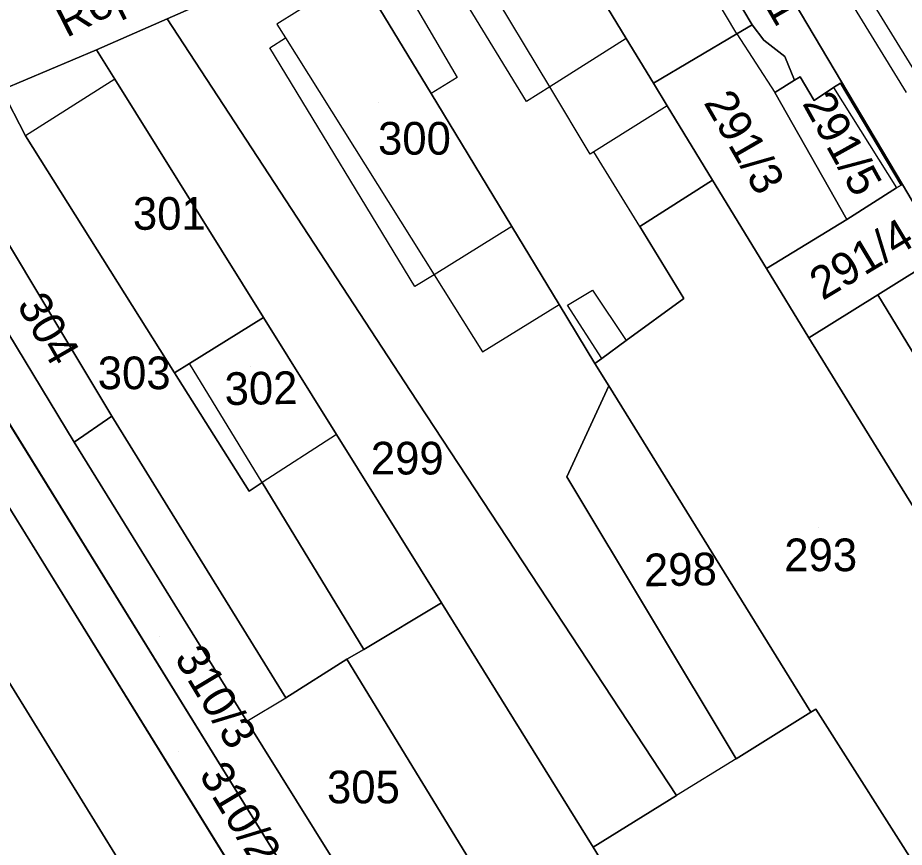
# Model space of a CAD drawing. Extents: x -263943 to -261149, y -1236934 to -1230686.
# Drawn here: x -262618.9 to -262564.6, y -1235644 to -1235593.2 of the extents above; entities that cross this region are included whole.
import ezdxf

# ---------------------------------------------------------------- set-up
doc = ezdxf.new("R2010")
doc.units = 0
for name, color, linetype in [('body_kn', 7, 'Continuous'), ('kladpar_druhypozemkov', 7, 'Continuous'), ('kladpar_hranice', 7, 'Continuous'), ('kladpar_parcelnecisla', 7, 'Continuous'), ('kladpar_plochy', 7, 'Continuous'), ('popisy', 7, 'Continuous'), ('zappar_hrandruhpozemk', 7, 'Continuous')]:
    doc.layers.add(name, color=color, linetype=linetype)

msp = doc.modelspace()

# ---------------------------------------------------------------- linework, layer by layer
at = {"layer": 'body_kn'}
for p, q in [((-262609.72, -1235593.27), (-262609.72, -1235593.27)), ((-262603, -1235593.61), (-262603, -1235593.61)), ((-262573.91, -1235593.64), (-262573.91, -1235593.64)), ((-262573.91, -1235593.64), (-262573.91, -1235593.64)), ((-262602.48, -1235594.44), (-262602.48, -1235594.44)), ((-262602.48, -1235594.44), (-262602.48, -1235594.44)), ((-262574.85, -1235594.19), (-262574.85, -1235594.19)), ((-262574.85, -1235594.19), (-262574.85, -1235594.19)), ((-262581.61, -1235594.48), (-262581.61, -1235594.48)), ((-262581.61, -1235594.48), (-262581.61, -1235594.48)), ((-262573.18, -1235594.59), (-262573.18, -1235594.59)), ((-262614.05, -1235595.18), (-262614.05, -1235595.18)), ((-262603.43, -1235595.05), (-262603.43, -1235595.05)), ((-262571.9, -1235595.58), (-262571.9, -1235595.58)), ((-262571.9, -1235595.58), (-262571.9, -1235595.58)), ((-262612.93, -1235596.98), (-262612.93, -1235596.98)), ((-262612.93, -1235596.98), (-262612.93, -1235596.98)), ((-262591.97, -1235596.87), (-262591.97, -1235596.87)), ((-262571.31, -1235597.03), (-262571.31, -1235597.03)), ((-262570.97, -1235596.82), (-262570.97, -1235596.82)), ((-262586.3, -1235597.44), (-262586.3, -1235597.44)), ((-262579.94, -1235597.22), (-262579.94, -1235597.22)), ((-262568.92, -1235597.49), (-262568.92, -1235597.49)), ((-262568.92, -1235597.49), (-262568.92, -1235597.49)), ((-262568.49, -1235597.22), (-262568.49, -1235597.22)), ((-262593.56, -1235597.85), (-262593.56, -1235597.85)), ((-262572.51, -1235597.78), (-262572.51, -1235597.78)), ((-262572.51, -1235597.78), (-262572.51, -1235597.78)), ((-262587.72, -1235598.33), (-262587.72, -1235598.33)), ((-262579.1, -1235598.6), (-262579.1, -1235598.6)), ((-262579.1, -1235598.6), (-262579.1, -1235598.6)), ((-262570.11, -1235598.27), (-262570.11, -1235598.27)), ((-262618.4, -1235600.43), (-262618.4, -1235600.43)), ((-262618.4, -1235600.43), (-262618.4, -1235600.43)), ((-262583.59, -1235601.41), (-262583.59, -1235601.41)), ((-262583.59, -1235601.41), (-262583.59, -1235601.41)), ((-262583.83, -1235601.56), (-262583.83, -1235601.56)), ((-262576.33, -1235603.15), (-262576.33, -1235603.15)), ((-262565.07, -1235603.63), (-262565.07, -1235603.63)), ((-262565.07, -1235603.63), (-262565.07, -1235603.63)), ((-262564.78, -1235603.46), (-262564.78, -1235603.46)), ((-262564.7, -1235603.41), (-262564.7, -1235603.41)), ((-262568.11, -1235605.57), (-262568.11, -1235605.57)), ((-262588.62, -1235605.99), (-262588.62, -1235605.99)), ((-262588.62, -1235605.99), (-262588.62, -1235605.99)), ((-262580.78, -1235605.99), (-262580.78, -1235605.99)), ((-262580.78, -1235605.99), (-262580.78, -1235605.99)), ((-262573.03, -1235608.57), (-262573.03, -1235608.57)), ((-262593.38, -1235608.94), (-262593.38, -1235608.94)), ((-262594.56, -1235609.67), (-262594.56, -1235609.67)), ((-262583.68, -1235609.88), (-262583.68, -1235609.88)), ((-262566.2, -1235610.17), (-262566.2, -1235610.17)), ((-262566.2, -1235610.17), (-262566.2, -1235610.17)), ((-262578.08, -1235610.4), (-262578.08, -1235610.4)), ((-262585.72, -1235610.76), (-262585.72, -1235610.76)), ((-262585.22, -1235610.81), (-262585.22, -1235610.81)), ((-262603.82, -1235611.57), (-262603.82, -1235611.57)), ((-262570.44, -1235612.81), (-262570.44, -1235612.81)), ((-262581.61, -1235612.97), (-262581.61, -1235612.97)), ((-262590.41, -1235613.67), (-262590.41, -1235613.67)), ((-262608.35, -1235614.37), (-262608.35, -1235614.37)), ((-262583.53, -1235614.37), (-262583.53, -1235614.37)), ((-262583.53, -1235614.37), (-262583.53, -1235614.37)), ((-262583.11, -1235614.07), (-262583.11, -1235614.07)), ((-262583.11, -1235614.07), (-262583.11, -1235614.07)), ((-262609.27, -1235614.94), (-262609.27, -1235614.94)), ((-262594.84, -1235616.03), (-262594.84, -1235616.03)), ((-262582.68, -1235615.74), (-262582.68, -1235615.74)), ((-262582.68, -1235615.74), (-262582.68, -1235615.74)), ((-262567.81, -1235617.07), (-262567.81, -1235617.07)), ((-262613.11, -1235617.59), (-262613.11, -1235617.59)), ((-262599.36, -1235618.72), (-262599.36, -1235618.72)), ((-262599.36, -1235618.72), (-262599.36, -1235618.72)), ((-262615.41, -1235619.19), (-262615.41, -1235619.19)), ((-262585.25, -1235621.32), (-262585.25, -1235621.32)), ((-262603.91, -1235621.67), (-262603.91, -1235621.67)), ((-262603.91, -1235621.67), (-262603.91, -1235621.67)), ((-262604.71, -1235622.19), (-262604.71, -1235622.19)), ((-262592.93, -1235629.02), (-262592.93, -1235629.02)), ((-262597.69, -1235631.89), (-262597.69, -1235631.89)), ((-262598.72, -1235632.48), (-262598.72, -1235632.48)), ((-262598.72, -1235632.48), (-262598.72, -1235632.48)), ((-262602.46, -1235634.84), (-262602.46, -1235634.84)), ((-262570.01, -1235635.54), (-262570.01, -1235635.54)), ((-262570.31, -1235635.73), (-262570.31, -1235635.73)), ((-262604.85, -1235636.28), (-262604.85, -1235636.28)), ((-262604.85, -1235636.28), (-262604.85, -1235636.28)), ((-262574.89, -1235638.57), (-262574.89, -1235638.57)), ((-262574.89, -1235638.57), (-262574.89, -1235638.57)), ((-262578.54, -1235640.83), (-262578.54, -1235640.83)), ((-262583.63, -1235643.98), (-262583.63, -1235643.98))]:
    msp.add_line(p, q, dxfattribs=at)
at = {"layer": 'kladpar_druhypozemkov'}
for p, q in [((-262596.8, -1235598.39), (-262596.8, -1235598.39)), ((-262573.34, -1235600.62), (-262573.34, -1235600.62)), ((-262567.56, -1235600.92), (-262567.56, -1235600.92)), ((-262610.05, -1235604.24), (-262610.05, -1235604.24)), ((-262567.91, -1235607.64), (-262567.91, -1235607.64)), ((-262611.9, -1235614.03), (-262611.9, -1235614.03)), ((-262604.65, -1235614.59), (-262604.65, -1235614.59)), ((-262595.9, -1235619.24), (-262595.9, -1235619.24)), ((-262569.85, -1235624.44), (-262569.85, -1235624.44)), ((-262578.8, -1235626.44), (-262578.8, -1235626.44)), ((-262610.17, -1235631.1), (-262610.17, -1235631.1)), ((-262609.01, -1235638.15), (-262609.01, -1235638.15)), ((-262598.15, -1235639.39), (-262598.15, -1235639.39))]:
    msp.add_line(p, q, dxfattribs=at)
at = {"layer": 'kladpar_hranice'}
for p, q in [((-262598.02, -1235652.59), (-262629.39, -1235601.96)), ((-262629.39, -1235601.96), (-262598.02, -1235652.59)), ((-262565.36, -1235710.5), (-262631.97, -1235602.9)), ((-262631.97, -1235602.9), (-262565.36, -1235710.5))]:
    msp.add_line(p, q, dxfattribs=at)
for points in [[(-262532.65, -1235562.1), (-262539.93, -1235564.98), (-262540.35, -1235564.47), (-262546.13, -1235566.81), (-262550.31, -1235568.5), (-262550.6, -1235568.62), (-262559.42, -1235572.29), (-262564.18, -1235574.14), (-262569.31, -1235576.04), (-262578.87, -1235579.57), (-262581.75, -1235580.64), (-262588.52, -1235583.14), (-262593.39, -1235585.64), (-262594.97, -1235586.46), (-262599.16, -1235588.62), (-262609.72, -1235593.27), (-262614.05, -1235595.18), (-262619.84, -1235597.63)], [(-262562.18, -1235607.66), (-262564.7, -1235603.41), (-262578.87, -1235579.57), (-262569.31, -1235576.04), (-262542, -1235620.28), (-262551.28, -1235626.02), (-262555.42, -1235619.05), (-262562.18, -1235607.66)], [(-262571.9, -1235595.58), (-262573.18, -1235594.59), (-262573.91, -1235593.64), (-262577.58, -1235587.46), (-262578.5, -1235588.03), (-262581.19, -1235583.29), (-262586.99, -1235585.65), (-262587.03, -1235585.58), (-262588.52, -1235583.14), (-262581.75, -1235580.64), (-262578.87, -1235579.57), (-262564.7, -1235603.41), (-262564.78, -1235603.46), (-262568.49, -1235597.22), (-262568.92, -1235597.49), (-262570.11, -1235598.27), (-262570.97, -1235596.82), (-262571.31, -1235597.03), (-262571.9, -1235595.58)], [(-262580.78, -1235605.99), (-262578.08, -1235610.4), (-262581.61, -1235612.97), (-262583.11, -1235614.07), (-262583.53, -1235614.37), (-262585.72, -1235610.76), (-262588.62, -1235605.99), (-262593.56, -1235597.85), (-262596.41, -1235593.15), (-262598.03, -1235590.49), (-262599.16, -1235588.62), (-262594.97, -1235586.46), (-262593.39, -1235585.64), (-262588.52, -1235583.14), (-262587.03, -1235585.58), (-262586.99, -1235585.65), (-262581.61, -1235594.48), (-262579.94, -1235597.22), (-262579.1, -1235598.6), (-262576.33, -1235603.15), (-262580.78, -1235605.99)], [(-262573.91, -1235593.64), (-262574.85, -1235594.19), (-262579.94, -1235597.22), (-262581.61, -1235594.48), (-262586.99, -1235585.65), (-262581.19, -1235583.29), (-262578.5, -1235588.03), (-262577.58, -1235587.46), (-262573.91, -1235593.64)], [(-262583.53, -1235614.37), (-262582.68, -1235615.74), (-262585.25, -1235621.32), (-262574.89, -1235638.57), (-262570.31, -1235635.73), (-262570.01, -1235635.54), (-262563.41, -1235645.91), (-262577.29, -1235654.35), (-262583.63, -1235643.98), (-262578.54, -1235640.83), (-262594.84, -1235616.03), (-262609.72, -1235593.27), (-262599.16, -1235588.62), (-262598.03, -1235590.49), (-262596.41, -1235593.15), (-262593.56, -1235597.85), (-262588.62, -1235605.99), (-262585.72, -1235610.76), (-262583.53, -1235614.37)], [(-262599.36, -1235618.72), (-262603.82, -1235611.57), (-262612.93, -1235596.98), (-262614.05, -1235595.18), (-262609.72, -1235593.27), (-262594.84, -1235616.03), (-262578.54, -1235640.83), (-262583.63, -1235643.98), (-262592.93, -1235629.02), (-262599.36, -1235618.72)], [(-262574.85, -1235594.19), (-262573.91, -1235593.64), (-262573.18, -1235594.59), (-262571.9, -1235595.58), (-262571.31, -1235597.03), (-262572.51, -1235597.78), (-262568.11, -1235605.57), (-262573.03, -1235608.57), (-262576.33, -1235603.15), (-262579.1, -1235598.6), (-262579.94, -1235597.22), (-262574.85, -1235594.19)], [(-262618.4, -1235600.43), (-262619.84, -1235597.63), (-262614.05, -1235595.18), (-262612.93, -1235596.98), (-262603.82, -1235611.57), (-262608.35, -1235614.37), (-262609.27, -1235614.94), (-262618.4, -1235600.43)], [(-262572.51, -1235597.78), (-262571.31, -1235597.03), (-262570.97, -1235596.82), (-262570.11, -1235598.27), (-262568.92, -1235597.49), (-262568.49, -1235597.22), (-262564.78, -1235603.46), (-262565.07, -1235603.63), (-262568.11, -1235605.57), (-262572.51, -1235597.78)], [(-262598.72, -1235632.48), (-262602.46, -1235634.84), (-262613.11, -1235617.59), (-262623.75, -1235599.9), (-262619.84, -1235597.63), (-262618.4, -1235600.43), (-262609.27, -1235614.94), (-262604.71, -1235622.19), (-262603.91, -1235621.67), (-262597.69, -1235631.89), (-262598.72, -1235632.48)], [(-262623.75, -1235599.9), (-262613.11, -1235617.59), (-262615.41, -1235619.19), (-262626.51, -1235600.91), (-262623.75, -1235599.9)], [(-262626.51, -1235600.91), (-262615.41, -1235619.19), (-262604.85, -1235636.28), (-262595.63, -1235651.07), (-262598.02, -1235652.59)], [(-262565.36, -1235710.5), (-262570.45, -1235713.76), (-262571.77, -1235711.63), (-262582.68, -1235693.86), (-262604.66, -1235658.08), (-262612.77, -1235644.65), (-262624.69, -1235625.35), (-262636.17, -1235606.78), (-262637.36, -1235604.86), (-262631.97, -1235602.9)], [(-262553.45, -1235640.26), (-262563.08, -1235646.46), (-262563.41, -1235645.91), (-262570.01, -1235635.54), (-262570.31, -1235635.73), (-262582.68, -1235615.74), (-262583.53, -1235614.37), (-262583.11, -1235614.07), (-262581.61, -1235612.97), (-262578.08, -1235610.4), (-262580.78, -1235605.99), (-262576.33, -1235603.15), (-262573.03, -1235608.57), (-262570.44, -1235612.81), (-262567.81, -1235617.07), (-262553.45, -1235640.26)], [(-262565.07, -1235603.63), (-262564.78, -1235603.46), (-262564.7, -1235603.41), (-262562.18, -1235607.66), (-262566.2, -1235610.17), (-262570.44, -1235612.81), (-262573.03, -1235608.57), (-262568.11, -1235605.57), (-262565.07, -1235603.63)], [(-262544.28, -1235646.18), (-262566.2, -1235610.17), (-262562.18, -1235607.66), (-262555.42, -1235619.05), (-262551.28, -1235626.02), (-262540.46, -1235644.04), (-262544.28, -1235646.18)], [(-262566.2, -1235610.17), (-262544.28, -1235646.18), (-262548.46, -1235648.51), (-262553.45, -1235640.26), (-262567.81, -1235617.07), (-262570.44, -1235612.81), (-262566.2, -1235610.17)], [(-262603.91, -1235621.67), (-262604.71, -1235622.19), (-262609.27, -1235614.94), (-262608.35, -1235614.37), (-262603.82, -1235611.57), (-262599.36, -1235618.72), (-262592.93, -1235629.02), (-262597.69, -1235631.89), (-262603.91, -1235621.67)], [(-262582.68, -1235615.74), (-262570.31, -1235635.73), (-262574.89, -1235638.57), (-262585.25, -1235621.32), (-262582.68, -1235615.74)], [(-262571.62, -1235689.74), (-262589.21, -1235661.27), (-262586.06, -1235659.24), (-262592.23, -1235648.96), (-262595.63, -1235651.07), (-262604.85, -1235636.28), (-262615.41, -1235619.19), (-262613.11, -1235617.59), (-262602.46, -1235634.84), (-262598.72, -1235632.48), (-262589.42, -1235647.7), (-262582.83, -1235658.83), (-262565.92, -1235686.28), (-262571.62, -1235689.74)], [(-262634.41, -1235631.7), (-262630.76, -1235629.31), (-262629.74, -1235628.64), (-262625.1, -1235625.62), (-262624.69, -1235625.35), (-262612.77, -1235644.65), (-262622.65, -1235650.47), (-262634.41, -1235631.7)], [(-262565.92, -1235686.28), (-262582.83, -1235658.83), (-262589.42, -1235647.7), (-262598.72, -1235632.48), (-262597.69, -1235631.89), (-262592.93, -1235629.02), (-262583.63, -1235643.98), (-262577.29, -1235654.35), (-262560.13, -1235682.74), (-262565.92, -1235686.28)]]:
    msp.add_lwpolyline(points, dxfattribs=at)
at = {"layer": 'kladpar_plochy'}
msp.add_lwpolyline([(-262532.65, -1235562.1), (-262539.93, -1235564.98), (-262540.35, -1235564.47), (-262546.13, -1235566.81), (-262550.31, -1235568.5), (-262550.6, -1235568.62), (-262559.42, -1235572.29), (-262564.18, -1235574.14), (-262569.31, -1235576.04), (-262578.87, -1235579.57), (-262581.75, -1235580.64), (-262588.52, -1235583.14), (-262593.39, -1235585.64), (-262594.97, -1235586.46), (-262599.16, -1235588.62), (-262609.72, -1235593.27), (-262614.05, -1235595.18), (-262619.84, -1235597.63)], dxfattribs=at)
for points in [[(-262562.18, -1235607.66), (-262564.7, -1235603.41), (-262578.87, -1235579.57), (-262569.31, -1235576.04), (-262542, -1235620.28), (-262551.28, -1235626.02), (-262555.42, -1235619.05)], [(-262571.9, -1235595.58), (-262573.18, -1235594.59), (-262573.91, -1235593.64), (-262577.58, -1235587.46), (-262578.5, -1235588.03), (-262581.19, -1235583.29), (-262586.99, -1235585.65), (-262587.03, -1235585.58), (-262588.52, -1235583.14), (-262581.75, -1235580.64), (-262578.87, -1235579.57), (-262564.7, -1235603.41), (-262564.78, -1235603.46), (-262568.49, -1235597.22), (-262568.92, -1235597.49), (-262570.11, -1235598.27), (-262570.97, -1235596.82), (-262571.31, -1235597.03)], [(-262580.78, -1235605.99), (-262578.08, -1235610.4), (-262581.61, -1235612.97), (-262583.11, -1235614.07), (-262583.53, -1235614.37), (-262585.72, -1235610.76), (-262588.62, -1235605.99), (-262593.56, -1235597.85), (-262596.41, -1235593.15), (-262598.03, -1235590.49), (-262599.16, -1235588.62), (-262594.97, -1235586.46), (-262593.39, -1235585.64), (-262588.52, -1235583.14), (-262587.03, -1235585.58), (-262586.99, -1235585.65), (-262581.61, -1235594.48), (-262579.94, -1235597.22), (-262579.1, -1235598.6), (-262576.33, -1235603.15)], [(-262573.91, -1235593.64), (-262574.85, -1235594.19), (-262579.94, -1235597.22), (-262581.61, -1235594.48), (-262586.99, -1235585.65), (-262581.19, -1235583.29), (-262578.5, -1235588.03), (-262577.58, -1235587.46)], [(-262583.53, -1235614.37), (-262582.68, -1235615.74), (-262585.25, -1235621.32), (-262574.89, -1235638.57), (-262570.31, -1235635.73), (-262570.01, -1235635.54), (-262563.41, -1235645.91), (-262577.29, -1235654.35), (-262583.63, -1235643.98), (-262578.54, -1235640.83), (-262594.84, -1235616.03), (-262609.72, -1235593.27), (-262599.16, -1235588.62), (-262598.03, -1235590.49), (-262596.41, -1235593.15), (-262593.56, -1235597.85), (-262588.62, -1235605.99), (-262585.72, -1235610.76)], [(-262599.36, -1235618.72), (-262603.82, -1235611.57), (-262612.93, -1235596.98), (-262614.05, -1235595.18), (-262609.72, -1235593.27), (-262594.84, -1235616.03), (-262578.54, -1235640.83), (-262583.63, -1235643.98), (-262592.93, -1235629.02)], [(-262574.85, -1235594.19), (-262573.91, -1235593.64), (-262573.18, -1235594.59), (-262571.9, -1235595.58), (-262571.31, -1235597.03), (-262572.51, -1235597.78), (-262568.11, -1235605.57), (-262573.03, -1235608.57), (-262576.33, -1235603.15), (-262579.1, -1235598.6), (-262579.94, -1235597.22)], [(-262618.4, -1235600.43), (-262619.84, -1235597.63), (-262614.05, -1235595.18), (-262612.93, -1235596.98), (-262603.82, -1235611.57), (-262608.35, -1235614.37), (-262609.27, -1235614.94)], [(-262572.51, -1235597.78), (-262571.31, -1235597.03), (-262570.97, -1235596.82), (-262570.11, -1235598.27), (-262568.92, -1235597.49), (-262568.49, -1235597.22), (-262564.78, -1235603.46), (-262565.07, -1235603.63), (-262568.11, -1235605.57)], [(-262598.72, -1235632.48), (-262602.46, -1235634.84), (-262613.11, -1235617.59), (-262623.75, -1235599.9), (-262619.84, -1235597.63), (-262618.4, -1235600.43), (-262609.27, -1235614.94), (-262604.71, -1235622.19), (-262603.91, -1235621.67), (-262597.69, -1235631.89)], [(-262623.75, -1235599.9), (-262613.11, -1235617.59), (-262615.41, -1235619.19), (-262626.51, -1235600.91)], [(-262626.51, -1235600.91), (-262615.41, -1235619.19), (-262604.85, -1235636.28), (-262595.63, -1235651.07), (-262598.02, -1235652.59), (-262629.39, -1235601.96)], [(-262562.99, -1235708.99), (-262565.36, -1235710.5), (-262631.97, -1235602.9), (-262629.39, -1235601.96), (-262598.02, -1235652.59), (-262591.76, -1235662.87)], [(-262565.36, -1235710.5), (-262570.45, -1235713.76), (-262571.77, -1235711.63), (-262582.68, -1235693.86), (-262604.66, -1235658.08), (-262612.77, -1235644.65), (-262624.69, -1235625.35), (-262636.17, -1235606.78), (-262637.36, -1235604.86), (-262631.97, -1235602.9)], [(-262553.45, -1235640.26), (-262563.08, -1235646.46), (-262563.41, -1235645.91), (-262570.01, -1235635.54), (-262570.31, -1235635.73), (-262582.68, -1235615.74), (-262583.53, -1235614.37), (-262583.11, -1235614.07), (-262581.61, -1235612.97), (-262578.08, -1235610.4), (-262580.78, -1235605.99), (-262576.33, -1235603.15), (-262573.03, -1235608.57), (-262570.44, -1235612.81), (-262567.81, -1235617.07)], [(-262565.07, -1235603.63), (-262564.78, -1235603.46), (-262564.7, -1235603.41), (-262562.18, -1235607.66), (-262566.2, -1235610.17), (-262570.44, -1235612.81), (-262573.03, -1235608.57), (-262568.11, -1235605.57)], [(-262544.28, -1235646.18), (-262566.2, -1235610.17), (-262562.18, -1235607.66), (-262555.42, -1235619.05), (-262551.28, -1235626.02), (-262540.46, -1235644.04)], [(-262566.2, -1235610.17), (-262544.28, -1235646.18), (-262548.46, -1235648.51), (-262553.45, -1235640.26), (-262567.81, -1235617.07), (-262570.44, -1235612.81)], [(-262603.91, -1235621.67), (-262604.71, -1235622.19), (-262609.27, -1235614.94), (-262608.35, -1235614.37), (-262603.82, -1235611.57), (-262599.36, -1235618.72), (-262592.93, -1235629.02), (-262597.69, -1235631.89)], [(-262582.68, -1235615.74), (-262570.31, -1235635.73), (-262574.89, -1235638.57), (-262585.25, -1235621.32)], [(-262571.62, -1235689.74), (-262589.21, -1235661.27), (-262586.06, -1235659.24), (-262592.23, -1235648.96), (-262595.63, -1235651.07), (-262604.85, -1235636.28), (-262615.41, -1235619.19), (-262613.11, -1235617.59), (-262602.46, -1235634.84), (-262598.72, -1235632.48), (-262589.42, -1235647.7), (-262582.83, -1235658.83), (-262565.92, -1235686.28)], [(-262634.41, -1235631.7), (-262630.76, -1235629.31), (-262629.74, -1235628.64), (-262625.1, -1235625.62), (-262624.69, -1235625.35), (-262612.77, -1235644.65), (-262622.65, -1235650.47)], [(-262565.92, -1235686.28), (-262582.83, -1235658.83), (-262589.42, -1235647.7), (-262598.72, -1235632.48), (-262597.69, -1235631.89), (-262592.93, -1235629.02), (-262583.63, -1235643.98), (-262577.29, -1235654.35), (-262560.13, -1235682.74)]]:
    msp.add_lwpolyline(points, close=True, dxfattribs=at)
at = {"layer": 'zappar_hrandruhpozemk'}
for p, q in [((-262574.15, -1235582), (-262564.48, -1235597.79)), ((-262574.85, -1235594.19), (-262578.5, -1235588.03)), ((-262594.75, -1235592.11), (-262591.97, -1235596.87)), ((-262587.72, -1235598.33), (-262591.69, -1235591.84)), ((-262603.43, -1235595.05), (-262602.48, -1235594.44)), ((-262602.48, -1235594.44), (-262593.38, -1235608.94)), ((-262574.85, -1235594.19), (-262572.51, -1235597.78)), ((-262581.61, -1235594.48), (-262586.3, -1235597.44)), ((-262594.56, -1235609.67), (-262603.43, -1235595.05)), ((-262612.93, -1235596.98), (-262618.4, -1235600.43)), ((-262591.97, -1235596.87), (-262593.56, -1235597.85)), ((-262586.3, -1235597.44), (-262587.72, -1235598.33)), ((-262568.92, -1235597.49), (-262565.07, -1235603.63)), ((-262579.1, -1235598.6), (-262583.59, -1235601.41)), ((-262580.78, -1235605.99), (-262583.59, -1235601.41)), ((-262588.62, -1235605.99), (-262593.38, -1235608.94)), ((-262593.38, -1235608.94), (-262594.56, -1235609.67)), ((-262583.68, -1235609.88), (-262581.61, -1235612.97)), ((-262603.91, -1235621.67), (-262608.35, -1235614.37)), ((-262599.36, -1235618.72), (-262603.91, -1235621.67)), ((-262604.85, -1235636.28), (-262602.46, -1235634.84)), ((-262574.89, -1235638.57), (-262578.54, -1235640.83))]:
    msp.add_line(p, q, dxfattribs=at)
for points in [[(-262561.1, -1235601.07), (-262563.51, -1235597.17), (-262573.24, -1235581.41)], [(-262586.3, -1235597.44), (-262590.24, -1235590.88), (-262591.68, -1235588.48)], [(-262598.03, -1235590.49), (-262603, -1235593.61), (-262602.48, -1235594.44)], [(-262583.59, -1235601.41), (-262583.83, -1235601.56), (-262586.3, -1235597.44)], [(-262593.38, -1235608.94), (-262590.41, -1235613.67), (-262585.72, -1235610.76)], [(-262583.11, -1235614.07), (-262585.22, -1235610.81), (-262583.68, -1235609.88)]]:
    msp.add_lwpolyline(points, dxfattribs=at)

# ---------------------------------------------------------------- texts
at = {"layer": 'kladpar_parcelnecisla'}
for s, rotation, p in [('291/1', 300, (-262575.709, -1235588.036)), ('291/3', 300, (-262576.905, -1235598.403)), ('291/5', 299, (-262570.863, -1235598.446)), ('291/4', 31, (-262569.59, -1235610.551)), ('304', 300, (-262618.962, -1235610.793)), ('303', 360, (-262613.975, -1235615.95)), ('302', 1, (-262606.192, -1235616.924)), ('299', 360, (-262597.256, -1235621.17)), ('298', 1, (-262580.511, -1235628.022)), ('310/3', 301, (-262609.318, -1235632.401)), ('310/2', 301, (-262607.81, -1235639.545))]:
    msp.add_text(s, height=2, rotation=rotation, dxfattribs=at).set_placement(p)
for s, p in [('300', (-262596.814, -1235601.59)), ('301', (-262611.823, -1235606.19)), ('293', (-262571.938, -1235627.09)), ('305', (-262599.938, -1235641.3))]:
    msp.add_text(s, height=2, dxfattribs=at).set_placement(p)
at = {"layer": 'popisy'}
msp.add_text('Repná', height=2, rotation=27, dxfattribs=at).set_placement((-262615.888, -1235594.459))

doc.saveas('drawing.dxf')
